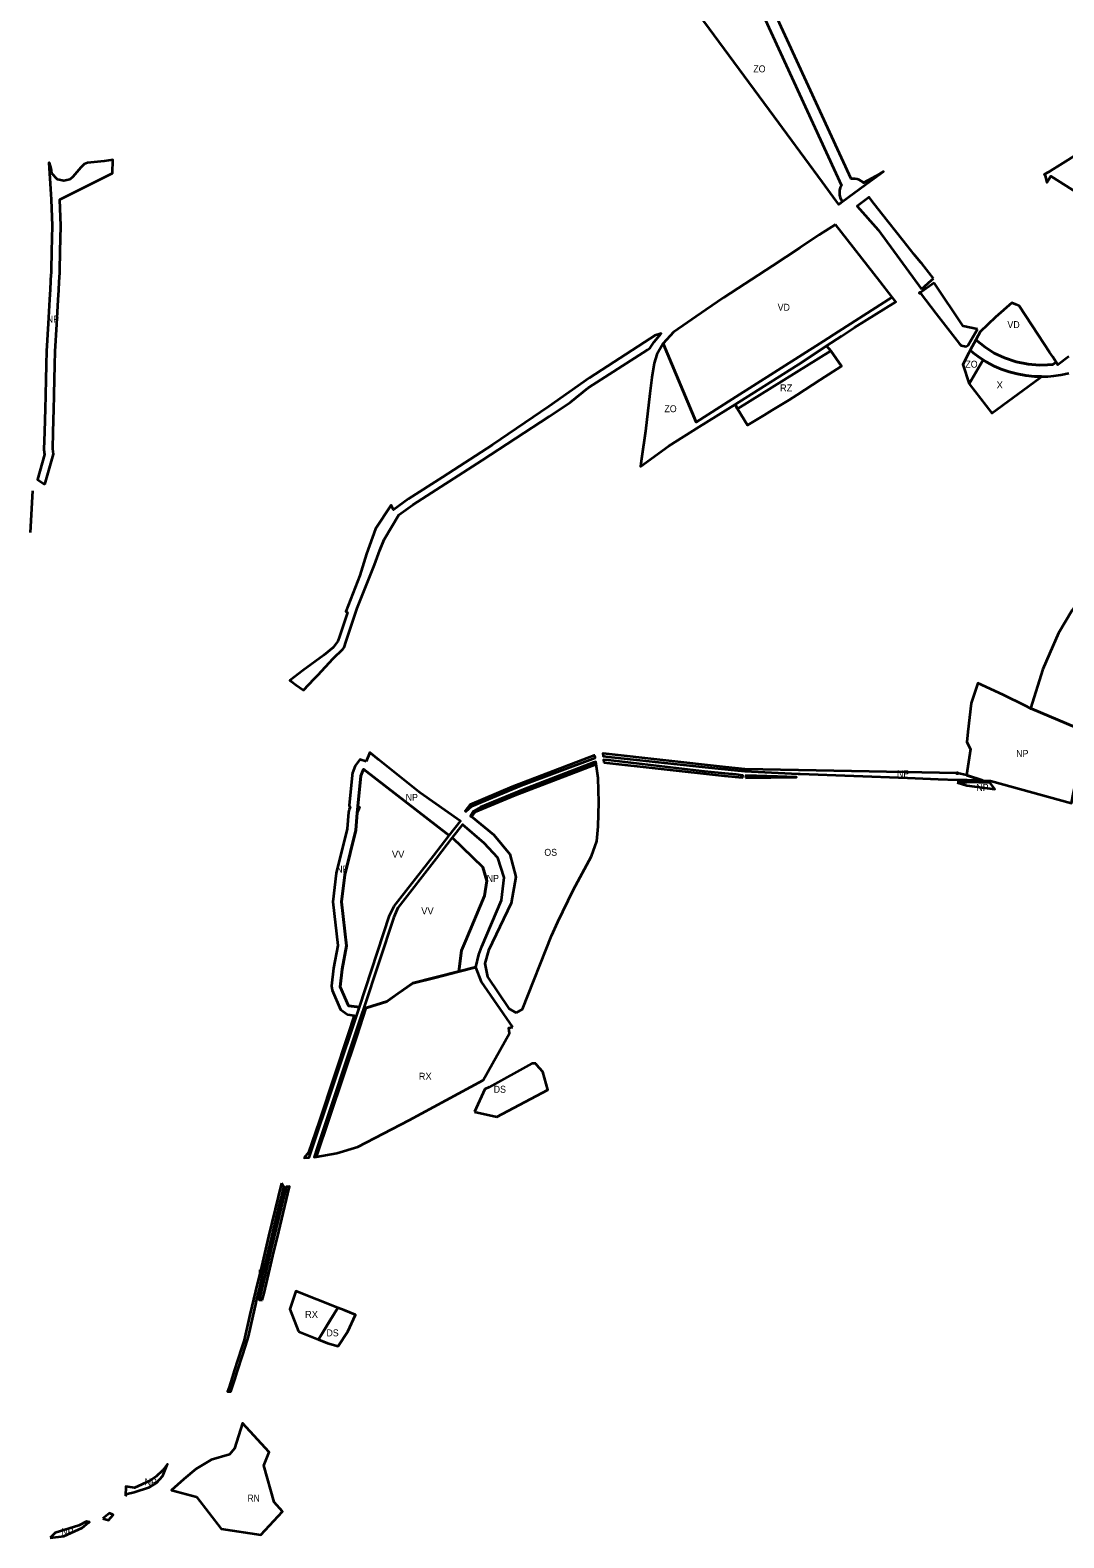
# Model space of a CAD drawing. Extents: x -650276 to -642489, y -1074311 to -1066658.
# Drawn here: x -649013 to -647227, y -1074311 to -1071706 of the extents above; entities that cross this region are included whole.
import ezdxf

# ---------------------------------------------------------------- set-up
doc = ezdxf.new("R2010")
doc.units = 0
doc.header["$LTSCALE"] = 4.8
doc.header["$PDMODE"] = 32
doc.header["$PDSIZE"] = 2.4
for name, color, linetype, lineweight in [('15', 7, 'Continuous', 35), ('24', 7, 'Continuous', 35), ('35', 7, 'Continuous', 35), ('42', 7, 'Continuous', 35), ('45', 7, 'Continuous', 35), ('46', 7, 'Continuous', 35), ('48', 7, 'Continuous', 35), ('5', 7, 'Continuous', 35), ('51', 7, 'Continuous', 35), ('54', 7, 'Continuous', 35), ('7', 7, 'Continuous', 35), ('8', 7, 'Continuous', 35), ('9', 7, 'Continuous', 35)]:
    doc.layers.add(name, color=color, linetype=linetype, lineweight=lineweight)
doc.layers.add('62', color=7, linetype='Continuous')

msp = doc.modelspace()

# ---------------------------------------------------------------- linework, layer by layer
at = {"layer": '15'}
msp.add_lwpolyline([(-647795.4, -1072352.415), (-647679.66, -1072279.15), (-647637.082, -1072251.377), (-647629.67, -1072259.82), (-647791.198, -1072360.119)], close=True, dxfattribs=at)
for points in [[(-647629.67, -1072259.82), (-647637.082, -1072251.377), (-647679.66, -1072279.15)], [(-647679.66, -1072279.15), (-647795.4, -1072352.415), (-647791.198, -1072360.119), (-647629.67, -1072259.82)]]:
    msp.add_lwpolyline(points, dxfattribs=at)
at = {"layer": '24'}
msp.add_line((-648245.341, -1073575.152), (-648207, -1073584), dxfattribs=at)
for points in [[(-647782.97, -1071619.278), (-647769.498, -1071636.647), (-647758.994, -1071653.513), (-647743.48, -1071687.426), (-647611.514, -1071974.086)], [(-647570.747, -1071972.644), (-647538.922, -1071950.099), (-647551.962, -1071958.049), (-647573.283, -1071969.627), (-647575.415, -1071967.709), (-647577.881, -1071965.979), (-647581.036, -1071964.346), (-647584.363, -1071963.196), (-647588.064, -1071962.51), (-647591.518, -1071962.387), (-647594.731, -1071962.714), (-647725.614, -1071678.405), (-647726.774, -1071675.885), (-647725.629, -1071678.373)], [(-647611.514, -1071974.086), (-647613.455, -1071978.031), (-647614.654, -1071982.238), (-647615.083, -1071986.65), (-647614.76, -1071990.762), (-647613.637, -1071995.081), (-647611.779, -1071999.069), (-647609.808, -1072001.962), (-647570.747, -1071972.644)], [(-647542.57, -1072021.99), (-647558.97, -1072000.62), (-647563.77, -1071994.38), (-647579.885, -1072006.501)], [(-647579.885, -1072006.501), (-647584.202, -1072009.747), (-647547.916, -1072050.439), (-647473.022, -1072153.375)], [(-647452.23, -1072134.91), (-647472.86, -1072109.13), (-647474.72, -1072106.81), (-647485.6, -1072093.2), (-647504.73, -1072069.29), (-647542.57, -1072021.99)], [(-647451.21, -1072142.08), (-647473.12, -1072157.91), (-647475.57, -1072159.74), (-647475.57, -1072159.74)], [(-647473.022, -1072153.375), (-647455.83, -1072137.96), (-647452.23, -1072134.91)], [(-647376.68, -1072222.29), (-647401.221, -1072217.342), (-647451.21, -1072142.08)], [(-647475.57, -1072159.74), (-647447.73, -1072195.72), (-647407.34, -1072247.93)], [(-647407.34, -1072247.93), (-647404.45, -1072250.66), (-647396.25, -1072252.14), (-647392.34, -1072250.02), (-647376.68, -1072222.29)], [(-647218.35, -1072269.67), (-647237.6, -1072283.78), (-647240.55, -1072279.42), (-647246.206, -1072283.328), (-647255.671, -1072284.192), (-647269.579, -1072284.489), (-647288.769, -1072283.003), (-647309.416, -1072278.875), (-647330.032, -1072271.935), (-647347.382, -1072263.623), (-647363.317, -1072253.632), (-647379.422, -1072240.675), (-647389.072, -1072258.845), (-647383.813, -1072263.219), (-647372.858, -1072271.363), (-647361.521, -1072278.584), (-647347.369, -1072286.111), (-647335.382, -1072291.341), (-647321.953, -1072296.073), (-647308.157, -1072299.786), (-647292.715, -1072302.646), (-647278.108, -1072304.147), (-647271.395, -1072304.452), (-647265.793, -1072304.439), (-647265.793, -1072304.439), (-647255.16, -1072304.123), (-647244.428, -1072303.192), (-647232.368, -1072301.4), (-647218.5, -1072298.335)], [(-648139.56, -1073491.4), (-648146.4, -1073491.55), (-648220.42, -1073532.43), (-648227.63, -1073535.89), (-648245.341, -1073575.152)], [(-648207, -1073584), (-648119, -1073537), (-648127.31, -1073505.75), (-648138.41, -1073493.62), (-648139.56, -1073491.4)]]:
    msp.add_lwpolyline(points, dxfattribs=at)
for points in [[(-648049.33, -1072323.77), (-647946.88, -1072257.82), (-647941.77, -1072254.45), (-647934.9, -1072244.55), (-647923.16, -1072229.85), (-647933.95, -1072233.18), (-647942.21, -1072238.54), (-648046.69, -1072306.3), (-648117.12, -1072356), (-648214.73, -1072422.41), (-648300.98, -1072478.1), (-648359.61, -1072515.85), (-648385.28, -1072534.41), (-648389.69, -1072526.36), (-648416.41, -1072567.43), (-648432.45, -1072610.56), (-648443.77, -1072648.02), (-648468.01, -1072710.44), (-648465.25, -1072712.03), (-648478.58, -1072753.49), (-648481.62, -1072761.39), (-648489.76, -1072772.74), (-648506.1, -1072785.56), (-648542.43, -1072812.6), (-648564.86, -1072829.45), (-648561.69, -1072831.54), (-648554.22, -1072836.89), (-648541.102, -1072846.281), (-648522.66, -1072826.92), (-648516.44, -1072820.39), (-648489.69, -1072791.37), (-648473.13, -1072775.58), (-648470.89, -1072772.42), (-648467.286, -1072761.426), (-648448.58, -1072704.37), (-648436.75, -1072675.79), (-648418.45, -1072629.91), (-648409.08, -1072604.25), (-648401.91, -1072586.1), (-648376.47, -1072543.52), (-648351.83, -1072525.81), (-648232.86, -1072449.45), (-648116.32, -1072373.44), (-648079.76, -1072348.46)], [(-648515.333, -1073968.584), (-648499.84, -1073974.76), (-648480.86, -1073980.25), (-648464.44, -1073954.69), (-648451.05, -1073925.87), (-648471, -1073918), (-648481.749, -1073913.76)]]:
    msp.add_lwpolyline(points, close=True, dxfattribs=at)
msp.add_point((-647475.57, -1072159.74), dxfattribs=at)
at = {"layer": '35'}
for points in [[(-647194.903, -1071913.941), (-647238.1, -1071941), (-647245.71, -1071945.77), (-647253.67, -1071950.76), (-647261.12, -1071954.82), (-647259.7, -1071957.06), (-647256.53, -1071968.64), (-647253.85, -1071964.38), (-647249.92, -1071958.12), (-647201.53, -1071988.71)], [(-647621.97, -1072041.73), (-647649.76, -1072059.06), (-647683.63, -1072081.94), (-647730.53, -1072112.84), (-647814.58, -1072167.67), (-647845.58, -1072188.94), (-647901.91, -1072227.6), (-647919.68, -1072247.09), (-647862.615, -1072383.084)], [(-647523.71, -1072167.071), (-647545.44, -1072139.35), (-647621.97, -1072041.73)], [(-647862.615, -1072383.084), (-647800.2, -1072343.615), (-647642.504, -1072242.974), (-647616.719, -1072226.154), (-647523.71, -1072167.071)]]:
    msp.add_lwpolyline(points, dxfattribs=at)
msp.add_lwpolyline([(-647246.563, -1072270.214), (-647251.85, -1072262.12), (-647271.38, -1072232.23), (-647304.32, -1072181.81), (-647310.33, -1072179.58), (-647317.33, -1072176.99), (-647345.42, -1072201.58), (-647372.1, -1072226.89), (-647375.551, -1072233.387), (-647379.422, -1072240.675), (-647363.317, -1072253.632), (-647347.382, -1072263.623), (-647330.032, -1072271.935), (-647309.416, -1072278.875), (-647288.769, -1072283.003), (-647269.579, -1072284.489), (-647255.671, -1072284.192), (-647246.206, -1072283.328), (-647240.55, -1072279.42)], close=True, dxfattribs=at)
at = {"layer": '42'}
for points in [[(-647743.48, -1071687.426), (-647611.514, -1071974.086), (-647613.455, -1071978.031), (-647614.654, -1071982.238), (-647615.083, -1071986.65), (-647614.76, -1071990.762), (-647613.637, -1071995.081), (-647611.779, -1071999.069), (-647609.808, -1072001.962), (-647616.12, -1072006.7), (-647621.06, -1072000), (-647644.38, -1071968.3), (-647705.291, -1071885.501), (-647727.85, -1071854.86), (-647857.52, -1071678.92)], [(-647637.082, -1072251.377), (-647611.306, -1072234.563), (-647589.02, -1072219.66), (-647517.51, -1072174.98), (-647523.71, -1072167.071), (-647616.719, -1072226.154), (-647642.504, -1072242.974), (-647800.2, -1072343.615)], [(-647800.2, -1072343.615), (-647862.615, -1072383.084), (-647919.68, -1072247.09), (-647930.36, -1072266.38), (-647934.86, -1072280.99), (-647939.26, -1072306.1), (-647942.54, -1072333.82), (-647950.2, -1072398.61), (-647956.786, -1072446.511), (-647958.82, -1072459.74), (-647910.27, -1072424.51), (-647857.52, -1072391.14), (-647795.4, -1072352.415)], [(-647795.4, -1072352.415), (-647679.66, -1072279.15), (-647637.082, -1072251.377)]]:
    msp.add_lwpolyline(points, dxfattribs=at)
msp.add_lwpolyline([(-647390.58, -1072316.75), (-647366.505, -1072275.41), (-647372.858, -1072271.363), (-647383.813, -1072263.219), (-647389.072, -1072258.845), (-647391.3, -1072263.04), (-647401.88, -1072283.4)], close=True, dxfattribs=at)
at = {"layer": '45'}
for points in [[(-648463.25, -1073392.125), (-648444.523, -1073394.235), (-648392.43, -1073235.98), (-648384.6, -1073219.54), (-648315.955, -1073131.889), (-648289.148, -1073097.66), (-648437.643, -1072982.601), (-648442.187, -1072994.5), (-648447.043, -1073046.967), (-648444.11, -1073048.69), (-648448.1, -1073058.393)], [(-648448.1, -1073058.393), (-648450.875, -1073088.375), (-648469.875, -1073165.5), (-648475.437, -1073212.375), (-648466.687, -1073288.25), (-648474.5, -1073328.75), (-648477.562, -1073358.875), (-648463.25, -1073392.125)], [(-648272.642, -1073332.558), (-648268, -1073296), (-648261, -1073280), (-648228, -1073202), (-648224, -1073176), (-648231, -1073152), (-648283.884, -1073101.15), (-648311.798, -1073137.127), (-648378.17, -1073222.67), (-648385.09, -1073238.58), (-648436.857, -1073395.099)], [(-648397.062, -1073384.375), (-648378.125, -1073370.875), (-648352.312, -1073353), (-648314.687, -1073343.25), (-648272.642, -1073332.558)], [(-648436.857, -1073395.099), (-648432.187, -1073395.625), (-648397.062, -1073384.375)]]:
    msp.add_lwpolyline(points, dxfattribs=at)
at = {"layer": '46'}
msp.add_lwpolyline([(-647284.75, -1072877.79), (-647282.31, -1072878.82), (-647192.718, -1072916.582), (-647187.445, -1072918.804), (-647172.48, -1072872.92), (-647155.72, -1072836.46), (-647136.69, -1072808.98), (-647079.74, -1072731.1), (-647025.04, -1072679.96), (-646953.2, -1072627.45), (-646957.5, -1072612.09), (-646973.68, -1072555.68), (-646989.01, -1072513.62), (-646991.24, -1072509.24), (-647063.38, -1072562.42), (-647088.397, -1072580.865), (-647088.4, -1072580.868), (-647146.21, -1072634.02), (-647172.36, -1072661.69), (-647198.77, -1072691.71), (-647212.92, -1072708.05), (-647236.54, -1072748.09), (-647252.29, -1072783.24), (-647263.58, -1072809.97)], close=True, dxfattribs=at)
at = {"layer": '48'}
for points in [[(-648988.248, -1072491.089), (-648973.238, -1072438.27), (-648974.424, -1072429.462), (-648973.655, -1072400.254), (-648972.605, -1072360.164), (-648972.025, -1072338.183), (-648971.955, -1072335.341), (-648970.605, -1072283.823), (-648970.001, -1072260.788), (-648967.285, -1072213.663), (-648964.865, -1072171.684), (-648963.895, -1072154.905), (-648963.052, -1072140.301), (-648962.27, -1072125.223), (-648962.165, -1072120.949), (-648961.355, -1072088.12), (-648960.263, -1072043.893), (-648962.195, -1071998.309), (-648871.27, -1071952.643), (-648870.458, -1071929.441), (-648885.56, -1071932.1), (-648914.45, -1071934.78), (-648919.79, -1071937.27), (-648925.64, -1071943.18), (-648939.51, -1071959.25), (-648944.69, -1071963.44), (-648955.25, -1071966.15), (-648966.01, -1071963.74), (-648975.65, -1071953.47), (-648976.85, -1071944.78), (-648979.85, -1071935.11), (-648980.94, -1071935.12), (-648977.48, -1071989.2), (-648976.91, -1071998.2), (-648975.27, -1072044.01), (-648976.35, -1072087.75), (-648977.16, -1072120.58), (-648977.26, -1072124.65), (-648977.3, -1072126.08), (-648977.33, -1072127.34), (-648978.03, -1072139.48), (-648978.87, -1072154.04), (-648979.84, -1072170.82), (-648982.26, -1072212.8), (-648984.99, -1072260.16), (-648985.6, -1072283.43), (-648986.31, -1072310.66), (-648986.95, -1072334.96), (-648987.02, -1072337.8), (-648987.6, -1072359.77), (-648988.65, -1072399.86), (-648989.45, -1072430.27), (-648988.27, -1072439.04), (-649000.851, -1072482.138)], [(-647293.317, -1072873.549), (-647293.351, -1072873.533), (-647331.82, -1072854.49), (-647375.92, -1072833.99), (-647387.64, -1072868.69), (-647392.96, -1072918.277), (-647394.87, -1072936.08), (-647388.62, -1072948.03), (-647395.47, -1072993.25), (-647367.45, -1073002.47), (-647353.78, -1073003.1), (-647213.99, -1073041.449), (-647210.396, -1073023.593), (-647207.176, -1073007.598), (-647192.93, -1072936.82), (-647187.445, -1072918.804), (-647192.718, -1072916.582), (-647282.31, -1072878.82), (-647284.75, -1072877.79)], [(-648037.595, -1072959.123), (-648038.877, -1072959.418), (-648180.651, -1073013.629), (-648253.635, -1073044.348), (-648261.902, -1073054.939), (-648260.27, -1073056.17), (-648250.04, -1073047.08), (-648178.89, -1073017.03), (-648165.13, -1073011.22), (-648037.17, -1072963.24)], [(-648251.027, -1073065.418), (-648250.491, -1073064.698), (-648244.214, -1073056.657), (-648175.061, -1073027.551), (-648035.592, -1072974.222), (-648036.2, -1072969.98), (-648040.06, -1072971.47), (-648161.07, -1073017.9), (-648235.47, -1073048.4), (-648247.16, -1073055.34), (-648252.64, -1073064.13)], [(-648022.279, -1072971.102), (-647813.331, -1072994.317), (-647782.72, -1072997.397), (-647781.65, -1072993.53), (-647793.59, -1072992.29), (-647813.2, -1072990.26), (-647848.15, -1072986.63), (-648014.58, -1072967.51), (-648022.74, -1072966.57)], [(-647777.337, -1072997.711), (-647689.11, -1072996.49), (-647721.83, -1072995.45), (-647776.77, -1072993.69)], [(-647411.34, -1073005.89), (-647394.782, -1073011.002), (-647346.22, -1073017.52), (-647354.76, -1073006.65), (-647394.59, -1073005.58), (-647395.08, -1073005.64), (-647397.74, -1073005.95), (-647400.27, -1073006.24), (-647400.76, -1073006.29), (-647403.05, -1073006.2)], [(-648231, -1073152), (-648224, -1073176), (-648228, -1073202), (-648261, -1073280), (-648268, -1073296), (-648272.642, -1073332.558), (-648243.08, -1073325.04), (-648237.98, -1073303.4), (-648232.64, -1073289.31), (-648198.7, -1073209.08), (-648194.2, -1073170.13), (-648205.04, -1073136.07), (-648228.91, -1073110.54), (-648266.38, -1073078.59), (-648283.884, -1073101.15)], [(-648518.867, -1073652.836), (-648499.399, -1073594.679), (-648449.599, -1073445.278), (-648433.206, -1073395.51), (-648436.857, -1073395.099), (-648440.74, -1073406.84), (-648517.47, -1073637.26), (-648522.79, -1073653.23), (-648518.867, -1073652.836)], [(-648612.186, -1073900.905), (-648609.231, -1073888.415), (-648599.275, -1073846.445), (-648592.044, -1073816.692), (-648586.715, -1073794.059), (-648565.224, -1073704.393), (-648565.224, -1073704.393), (-648570.99, -1073704.56), (-648571.72, -1073707.63), (-648573.46, -1073714.88), (-648576.05, -1073725.82), (-648579.57, -1073740.47), (-648592.17, -1073793.18), (-648597.23, -1073814.32), (-648601.98, -1073834.2), (-648606.83, -1073854.48), (-648613.78, -1073883.59), (-648617.72, -1073900.06)], [(-648848.696, -1074238.993), (-648845.424, -1074235.305), (-648833.449, -1074232.685), (-648807.065, -1074223.704), (-648794.902, -1074216.219), (-648783.863, -1074204.056), (-648775.93, -1074183.91), (-648784.8, -1074195.26), (-648795.65, -1074205.35), (-648806.55, -1074212.62), (-648833.11, -1074225.2), (-648844.05, -1074223.24), (-648848.28, -1074222.49)], [(-648978.575, -1074311.426), (-648955.265, -1074308.325), (-648923.698, -1074294.313), (-648912.63, -1074284.912), (-648910.988, -1074284.211), (-648915.73, -1074283.08), (-648929.03, -1074290.14), (-648970.3, -1074302.9)], [(-648887.619, -1074278.134), (-648877.799, -1074280.64), (-648870.041, -1074271.932), (-648876.21, -1074268.73)]]:
    msp.add_lwpolyline(points, close=True, dxfattribs=at)
for points in [[(-648437.643, -1072982.601), (-648289.148, -1073097.66), (-648269.78, -1073072.93), (-648339.58, -1073023.82), (-648341.495, -1073022.285), (-648411.09, -1072966.5), (-648426.547, -1072954.108), (-648432.527, -1072969.463)], [(-647685.748, -1072984.544), (-647778.296, -1072982.767), (-647811.752, -1072979.4), (-648023.495, -1072955.875), (-648023.818, -1072955.949), (-648023.37, -1072960.37), (-648014.16, -1072961.36), (-647846.85, -1072979.37), (-647790.52, -1072985.06), (-647778.3, -1072986.29), (-647686.14, -1072990.78)], [(-648432.527, -1072969.463), (-648443.591, -1072965.983), (-648451.657, -1072977.25), (-648456.2, -1072989.149), (-648457.123, -1072993.118), (-648461.979, -1073045.585), (-648460.355, -1073048.753), (-648461.973, -1073052.688), (-648463.036, -1073057.011), (-648465.708, -1073085.876), (-648484.661, -1073162.812), (-648490.539, -1073212.35), (-648481.853, -1073287.675), (-648489.355, -1073326.567), (-648492.485, -1073357.358), (-648491.34, -1073364.805), (-648477.028, -1073398.055), (-648464.929, -1073407.031), (-648453.228, -1073408.349), (-648463.838, -1073440.559), (-648513.627, -1073589.927), (-648532.252, -1073645.567), (-648539.599, -1073654.802), (-648531.31, -1073654.08), (-648444.523, -1073394.235), (-648448.434, -1073393.794), (-648463.25, -1073392.125), (-648477.562, -1073358.875), (-648474.5, -1073328.75), (-648466.687, -1073288.25), (-648475.437, -1073212.375), (-648469.875, -1073165.5), (-648450.875, -1073088.375), (-648448.1, -1073058.393), (-648447.043, -1073046.967), (-648442.187, -1072994.5), (-648437.643, -1072982.601)], [(-647411.294, -1072989.813), (-647411.298, -1072989.813), (-647685.748, -1072984.544)], [(-647686.14, -1072990.78), (-647682.74, -1072990.95), (-647497.35, -1072997.93), (-647444.42, -1072999.87), (-647411.326, -1073001.08)], [(-647411.326, -1073001.08), (-647410.791, -1073001.197), (-647410.79, -1073001.1), (-647402.49, -1073001.41), (-647400.55, -1073001.48), (-647394.46, -1073001.23), (-647367.45, -1073002.47), (-647395.47, -1072993.25), (-647411.293, -1072989.813), (-647411.294, -1072989.813)], [(-648579.272, -1073698.648), (-648601.309, -1073790.592), (-648606.633, -1073813.202), (-648613.86, -1073842.943), (-648623.827, -1073884.957), (-648633.591, -1073926.228), (-648643.415, -1073969.782), (-648647.944, -1073983.639), (-648660.613, -1074022.822), (-648664.22, -1074034.155)], [(-648659.85, -1074037.72), (-648655.5, -1074024.36), (-648645.7, -1073994.3), (-648638.15, -1073971.13), (-648636.34, -1073963.19), (-648628.21, -1073927.61), (-648623.58, -1073907.34), (-648622.06, -1073901.02), (-648617.77, -1073883.09), (-648616.76, -1073878.91), (-648611.69, -1073857.74), (-648607.72, -1073841.19), (-648607.4, -1073839.84), (-648595.71, -1073791.1), (-648588.06, -1073759.19), (-648584.69, -1073745.15), (-648581.82, -1073733.14), (-648578.69, -1073720.11), (-648574.99, -1073704.67), (-648579.272, -1073698.648)], [(-648664.22, -1074034.155), (-648669.584, -1074051.005), (-648672.336, -1074058.391), (-648672.336, -1074058.391), (-648666.67, -1074058.64), (-648659.85, -1074037.72)]]:
    msp.add_lwpolyline(points, dxfattribs=at)
msp.add_point((-647411.294, -1072989.813), dxfattribs=at)
at = {"layer": '5'}
for points in [[(-648272.642, -1073332.558), (-648352.312, -1073353), (-648397.062, -1073384.375)], [(-648179.07, -1073428.81), (-648233.36, -1073350.68), (-648243.08, -1073325.04), (-648272.642, -1073332.558)], [(-648397.062, -1073384.375), (-648432.187, -1073395.625), (-648433.206, -1073395.51), (-648449.599, -1073445.278)], [(-648449.599, -1073445.278), (-648518.867, -1073652.836), (-648483.58, -1073646.7), (-648447.06, -1073635.39), (-648447.06, -1073635.39)], [(-648447.06, -1073635.39), (-648358.69, -1073589.35), (-648230.81, -1073520.18), (-648185.34, -1073438.91), (-648185.82, -1073435.12), (-648186.46, -1073430.01), (-648183.46, -1073429.52), (-648179.07, -1073428.81)]]:
    msp.add_lwpolyline(points, dxfattribs=at)
msp.add_lwpolyline([(-648549.76, -1073954.86), (-648515.333, -1073968.584), (-648498, -1073940), (-648481.749, -1073913.76), (-648554.42, -1073885.092), (-648564.75, -1073915.91)], close=True, dxfattribs=at)
at = {"layer": '51'}
msp.add_lwpolyline([(-647390.58, -1072316.75), (-647351.86, -1072367.52), (-647269.52, -1072307.17), (-647265.793, -1072304.439), (-647271.395, -1072304.452), (-647278.108, -1072304.147), (-647292.715, -1072302.646), (-647308.157, -1072299.786), (-647321.953, -1072296.073), (-647335.382, -1072291.341), (-647347.369, -1072286.111), (-647361.521, -1072278.584), (-647366.505, -1072275.41)], close=True, dxfattribs=at)
at = {"layer": '54'}
msp.add_line((-649009.031, -1072501.969), (-649013.32, -1072573.664), dxfattribs=at)
at = {"layer": '7'}
msp.add_lwpolyline([(-648725.93, -1074240.58), (-648683.5, -1074296.12), (-648683.5, -1074296.12), (-648614.6, -1074306.17), (-648577.25, -1074266.06), (-648591.67, -1074249.72), (-648609.49, -1074186.61), (-648600.53, -1074163.47), (-648646.42, -1074113.19), (-648660.16, -1074156.75), (-648669.01, -1074167.27), (-648700.45, -1074176.73), (-648726.23, -1074192.02), (-648747.74, -1074210.12), (-648768.94, -1074229.25), (-648725.93, -1074240.58), (-648725.93, -1074240.58)], close=True, dxfattribs=at)
at = {"layer": '8'}
msp.add_lwpolyline([(-647629.67, -1072259.82), (-647611.51, -1072286.26), (-647648.09, -1072309.95), (-647688.26, -1072336.06), (-647702.35, -1072345.14), (-647716.62, -1072353.95), (-647730.97, -1072362.6), (-647745.32, -1072371.26), (-647759.68, -1072379.91), (-647774.04, -1072388.57), (-647791.198, -1072360.119)], close=True, dxfattribs=at)
for points in [[(-647629.67, -1072259.82), (-647791.198, -1072360.119), (-647774.04, -1072388.57)], [(-647774.04, -1072388.57), (-647759.68, -1072379.91), (-647745.32, -1072371.26), (-647730.97, -1072362.6), (-647716.62, -1072353.95), (-647702.35, -1072345.14), (-647688.26, -1072336.06), (-647648.09, -1072309.95), (-647611.51, -1072286.26), (-647629.67, -1072259.82)]]:
    msp.add_lwpolyline(points, dxfattribs=at)
at = {"layer": '9'}
for points in [[(-648030.86, -1073039.71), (-648032.09, -1072998.65), (-648035.592, -1072974.222), (-648175.061, -1073027.551), (-648244.214, -1073056.657), (-648250.491, -1073064.698), (-648212.22, -1073096.39), (-648184.37, -1073129.89)], [(-648101.67, -1073246.63), (-648075.34, -1073191.93), (-648043.29, -1073132.97), (-648034.43, -1073107.07), (-648031.8, -1073082.07), (-648030.86, -1073039.71)], [(-648184.37, -1073129.89), (-648174.03, -1073168.94), (-648182.12, -1073214.56), (-648221.39, -1073296.24), (-648227.75, -1073318.75), (-648223.03, -1073341.59), (-648186.47, -1073396.47), (-648173.38, -1073404.03)], [(-648173.38, -1073404.03), (-648162.55, -1073397.4), (-648112.36, -1073270.87), (-648101.67, -1073246.63)]]:
    msp.add_lwpolyline(points, dxfattribs=at)

# ---------------------------------------------------------------- texts
at = {"layer": '62'}
for s, width, p in [('ZO', 0.95, (-647763.886, -1071778.486)), ('NP', 0.95, (-648984.583, -1072211.041)), ('VD', 0.95, (-647721.74, -1072190.495)), ('VD', 0.95, (-647324.74, -1072220.495)), ('ZO', 0.95, (-647397.457, -1072288.915)), ('ZO', 0.95, (-647917.457, -1072365.915)), ('NP', 0.95, (-647309.627, -1072961.756)), ('NP', 0.95, (-647515.505, -1072996.594)), ('NP', 0.95, (-647378.505, -1073020.594)), ('NP', 0.95, (-648364.505, -1073037.594)), ('OS', 0.95, (-648124.882, -1073132.612)), ('NP', 0.95, (-648484.505, -1073161.594)), ('NP', 0.95, (-648224.505, -1073177.594)), ('DS', 0.95, (-648212.386, -1073542.148)), ('NP', 0.95, (-648619.524, -1073859.849)), ('DS', 0.95, (-648501.386, -1073963.148)), ('NP', 0.95, (-648815.524, -1074220.849)), ('RN', 0.9, (-648637.627, -1074248.756)), ('NP', 0.95, (-648959.524, -1074306.849))]:
    msp.add_text(s, height=12, dxfattribs=dict(at, width=width)).set_placement(p)
for s, p in [('RZ', (-647717.713, -1072329.92)), ('X', (-647343.371, -1072324.801)), ('VV', (-648388.203, -1073135.952)), ('VV', (-648337.553, -1073233.772)), ('RX', (-648341.882, -1073519.612)), ('RX', (-648538.32, -1073931.277))]:
    msp.add_text(s, height=12, dxfattribs=at).set_placement(p)

doc.saveas('drawing.dxf')
